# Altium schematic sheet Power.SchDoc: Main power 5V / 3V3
size A4; Date: Not used; ApprovedBy: Not used; CheckedBy: Not used; Author: Not used; CompanyName: STMicroelectronics; DrawnBy: Not used; Engineer: Not used; Organization: Not used; Address1: Not used; Address2: Not used; Address3: Not used; Address4: Not used; DocumentNumber: 6; Revision: Not used; SheetNumber: 6; SheetTotal: 8
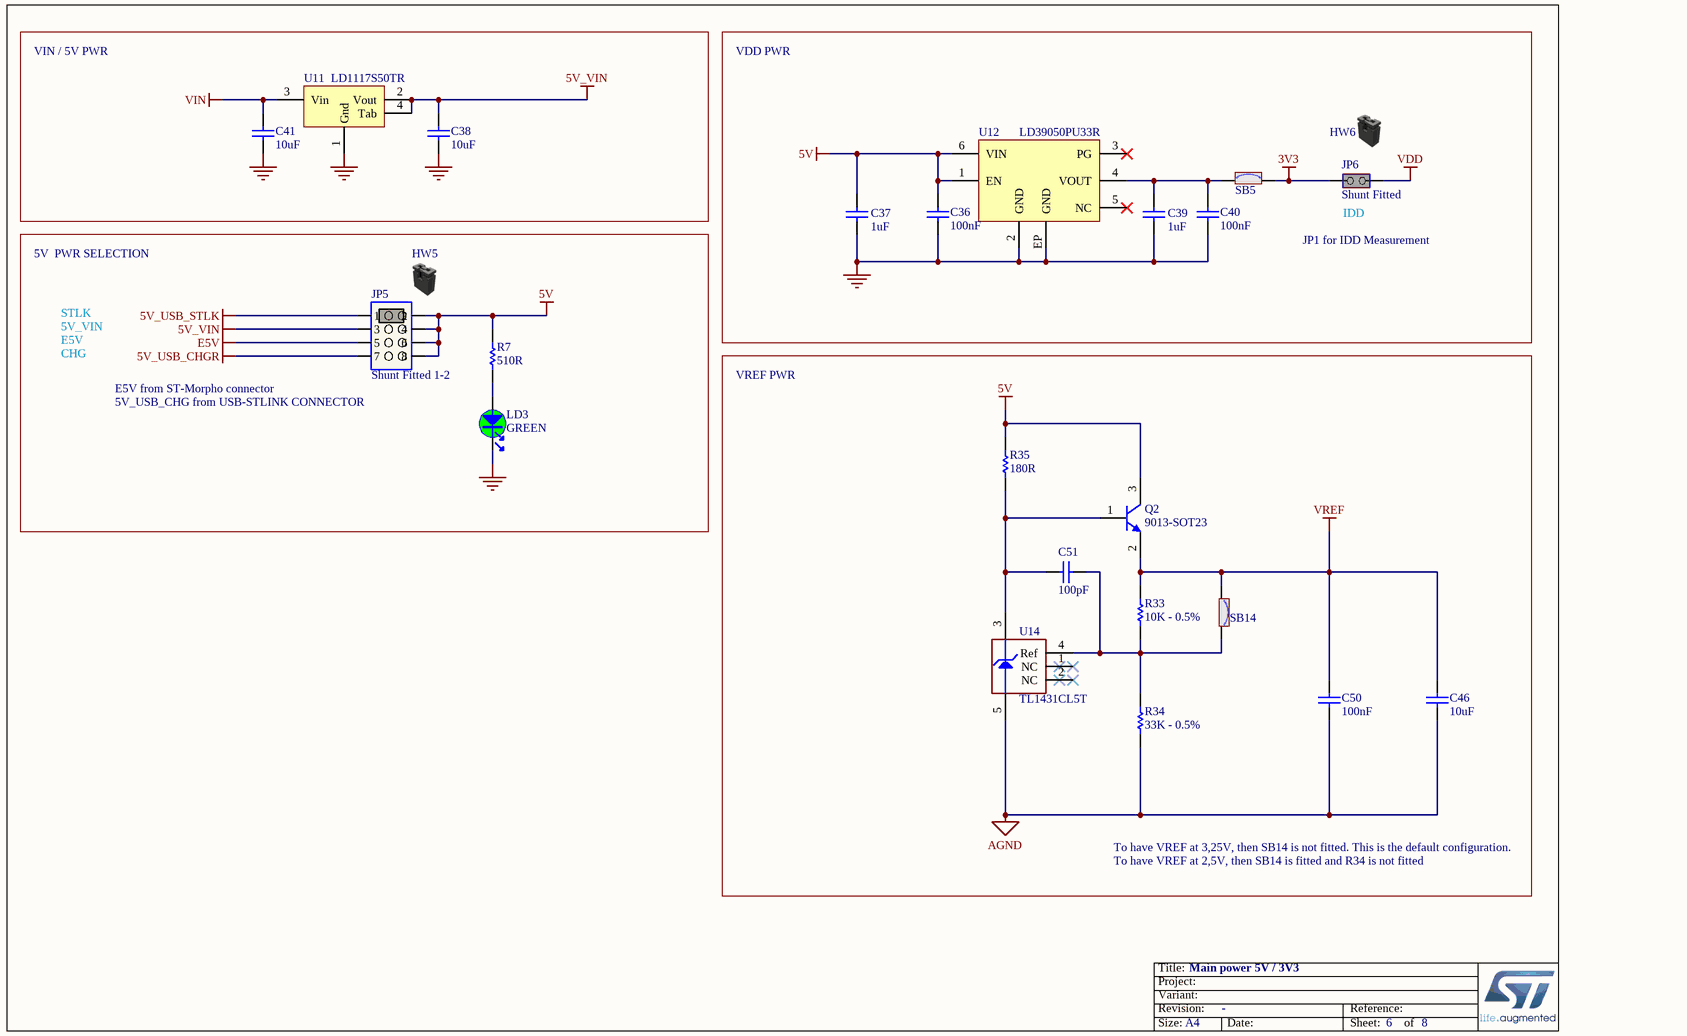
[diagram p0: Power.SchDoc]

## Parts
C36  value 100nF  [C0402]
C37  value 1uF  [C0603]
C38  value 10uF  [C0805]
C39  value 1uF  [C0603]
C40  value 100nF  [C0402]
C41  value 10uF  [C0805]
C46  value 10uF  [C0603]  (hidden comment: Capacitor)
C50  value 100nF  [C0603]
C51  value 100pF  [C0603]  (hidden comment: Capacitor)
HW5  (no value)  (mechanical)
HW6  (no value)  (mechanical)
JP5  Shunt Fitted 1-2  [CON_SAMTEC_TSW-104-07-X-D]
JP6  Shunt Fitted  [CON_SAMTEC_TSW-102-07-G-S]
LD3  value GREEN  [LED_0603_GREEN]
Q2  value 9013-SOT23  [NPN_SOT23]
R7  value 510R  [R0603]
R33  value 10K - 0.5%  [R0603]  (hidden comment: ​Add 0.5% tolerance resistor)
R34  value 33K - 0.5%  [R0603]  (hidden comment: ​add 0.5% tolerance resistor)
R35  value 180R  [R0603]  (hidden comment: Resistor)
SB5  (no value)  [SOLDER-BRIDGE_R0603-0R]
SB14  (no value)  [SOLDER-BRIDGE_R0603-0R]
U11  value LD1117S50TR  [REG_SOT223-TAB]
U12  value LD39050PU33R  [ICC_DFN6-EPAD_3X3_P095]
U14  value TL1431CL5T  [ICC_SOT23-5L_H1P45]  (hidden comment: TL1431ACL5T)

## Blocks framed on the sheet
VIN / 5V PWR: C38 C41 U11
VREF PWR: C46 C50 C51 Q2 R33-R35 SB14 U14

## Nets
3V3: JP6.1(COMMON) SB5.2
5V: C36.2 C37.2 JP5.2 JP5.4 JP5.6 JP5.8 Q2.3(C) R7.2 R35.2 U12.1(EN) U12.6(VIN)
5V_USB_CHGR: JP5.7
5V_USB_STLK: JP5.1
5V_VIN: C38.2 JP5.3 U11.2(Vout) U11.4(Tab)
AGND: C46.1 C50.1 R34.1 U14.5(Anode)
E5V: JP5.5
GND: C36.1 C37.1 C38.1 C39.1 C40.1 C41.1 LD3.2 U11.1(Gnd) U12.2(GND) U12.EP(GND)
VDD: JP6.2(NO)
VIN: C41.2 U11.3(Vin)
VREF: C46.2 C50.2 Q2.2(E) R33.2 SB14.1
NetC39_2: C39.2 C40.2 SB5.1 U12.4(VOUT)
NetC51_1: C51.1 Q2.1(B) R35.1 U14.3(Cathode)
NetC51_2: C51.2 R33.1 R34.2 SB14.2 U14.4(Ref)
NetLD3_1: LD3.1 R7.1

Not connected (* = marked no-connect by the designer): U12 3(PG)* 5(NC)*; U14 1(NC)* 2(NC)*

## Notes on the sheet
- VDD PWR
- JP1 for IDD Measurement
- (near JP6) IDD
- 5V  PWR SELECTION
- STLK
- E5V
- 5V_VIN
- CHG
- E5V from ST-Morpho connector
- 5V_USB_CHG from USB-STLINK CONNECTOR
- To have VREF at 3,25V, then SB14 is not fitted. This is the default configuration.
- To have VREF at 2,5V, then SB14 is fitted and R34 is not fitted

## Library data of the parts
C36 C40 = MCD-00102: Capacitor, MLCC, 100nF, 16V, X7R, 10%, 0402, T=0,5mm; Manufacturer_Part_Number: CC0402KRX7R7BB104; Manufacturer: YAGEO; Provided_By: Subcon; Initial_Board_Reference: MB1262
C37 C39 = MCD-00010: Capacitor, MLCC, 1uF, 16V, X5R, 10%, 0603, T=0,8mm; Manufacturer_Part_Number: CC0603KRX5R7BB105; Manufacturer: YAGEO; Provided_By: Subcon; Initial_Board_Reference: MB1274
C38 C41 = MCD-00014: Capacitor, MLCC, 10uF, 25V, X5R, 10%, 0805, T=0,85mm; Manufacturer_Part_Number: CC0805KRX5R8BB106; Manufacturer: YAGEO; Provided_By: Subcon; Initial_Board_Reference: MB1274
C46 = MCD-01124: Capacitor, MLCC, 10µF, 10V, X5R, 10%, 0603, T=0.8mm; Manufacturer_Part_Number: GRM188R61A106KAAL; Manufacturer: MURATA; ECCN_US: EAR99; ECCN_EU: NEC; Provided_By: Subcon; Initial_Board_Reference: MB1361
C50 = MCD-00211: Capacitor, MLCC, 100nF, 16V, X7R, 10%, 0603, T=0,8mm; Manufacturer_Part_Number: CC0603KRX7R7BB104; Manufacturer: YAGEO; Provided_By: Subcon; Initial_Board_Reference: MB1319
C51 = MCD-01101: Capacitor,100pF,50V,X7R,10%,0603; Manufacturer_Part_Number: 06035C101JAT4A; Manufacturer: AVX; Provided_By: Subcon; Initial_Board_Reference: MB1381
HW5 HW6 = MCD-00043: SHUNT 2.54mm BLACK; Manufacturer_Part_Number: SNT-100-BK-G; Manufacturer: SAMTEC; Part_Type: Mechanical; Provided_By: Subcon; Initial_Board_Reference: MB1274
JP5 = MCD-00686: Header, 4x2, 2,54mm, VR, TH, Height 5.84mm/2.54mm - Shunt Fitted 1-2; Part_Type: Connector; Manufacturer_Part_Number: TSW-104-07-x-D; Manufacturer: SAMTEC; Provided_By: Subcon; Initial_Board_Reference: MB1331
JP6 = MCD-00683: Header, 2x1, 2,54mm, VR, TH, Height 5.84mm/2.54mm - Shunt Fitted by default; Part_Type: Connector; Manufacturer_Part_Number: TSW-102-07-x-S; Manufacturer: SAMTEC; Provided_By: Subcon; Initial_Board_Reference: MB1331
LD3 = MCD-00050: LED, Green, 0603; Manufacturer_Part_Number: 19-213SYGC/S530-E2/TR8; Manufacturer: EVERLIGHT; Part_Type: Display; ECCN_US: EAR99; ECCN_EU: NEC; Provided_By: Subcon; Initial_Board_Reference: MB1274
Q2 = MCD-00073: NPN Bipolar Transistor; Part_Type: IC; Manufacturer_Part_Number: BSR14; Manufacturer: NXP; ECCN_US: EAR99; ECCN_EU: NEC; Provided_By: Subcon; Initial_Board_Reference: MB1274
R7 = MCD-00225: Resistor,510R,0603,1%,1/10W; Manufacturer_Part_Number: RC0603FR-07510RL; Manufacturer: YAGEO; Provided_By: Subcon; Initial_Board_Reference: MB1319
R33 = MCD-01215: resistor, 10K, 0603, 0.5%, 1/10W; Manufacturer_Part_Number: RC0603DR-0710KL; Manufacturer: YAGEO; ECCN_US: NA; Provided_By: Subcon; Initial_Board_Reference: MB1367
R34 = MCD-01209: Resistor,33K,0603,0.5%,1/10W; Manufacturer_Part_Number: RC0603DR-0733KL; Manufacturer: YAGEO; Provided_By: Subcon; Initial_Board_Reference: MB1367
R35 = MCD-00342: Resistor,180R,0603,1%,1/10W; Manufacturer_Part_Number: RC0603FR-07180RL; Manufacturer: YAGEO; ECCN_US: EAR99; ECCN_EU: NEC; Provided_By: SUBCO
SB5 SB14 = MCD-00071: Solder Bridge ON; Part_Type: Mechanical; Provided_By: Subcon; Initial_Board_Reference: MB1274
U11 = MCD-00088: IC REG LDO 5V 0.8A SOT223; Manufacturer: STMICROELECTRONICS; ECCN_US: EAR99; ECCN_EU: NEC; Provided_By: Subcon; Initial_Board_Reference: MB1274
U12 = MCD-00215: Low quiescent current and low noise voltage regulators; Manufacturer: STMICROELECTRONICS; Part_Type: IC; ECCN_US: EAR99; ECCN_EU: NEC; Provided_By: Subcon; Initial_Board_Reference: MB1319
U14 = MCD-01802: Programmable voltage reference with 0.4% voltage precision; Part_Type: IC; Manufacturer: STMICROELECTRONICS; ECCN_US: EAR99; ECCN_EU: NEC; Provided_By: SUBCO with ST control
